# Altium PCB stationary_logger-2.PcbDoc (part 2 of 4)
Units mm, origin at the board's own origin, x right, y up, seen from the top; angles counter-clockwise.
Board outline 105 x 45 mm, 4 copper layers (Top Layer, Layer 2, Layer 3, Bottom Layer), stack 1.492 mm thick; 317 components, 187 nets, 816 pads, 302 vias.
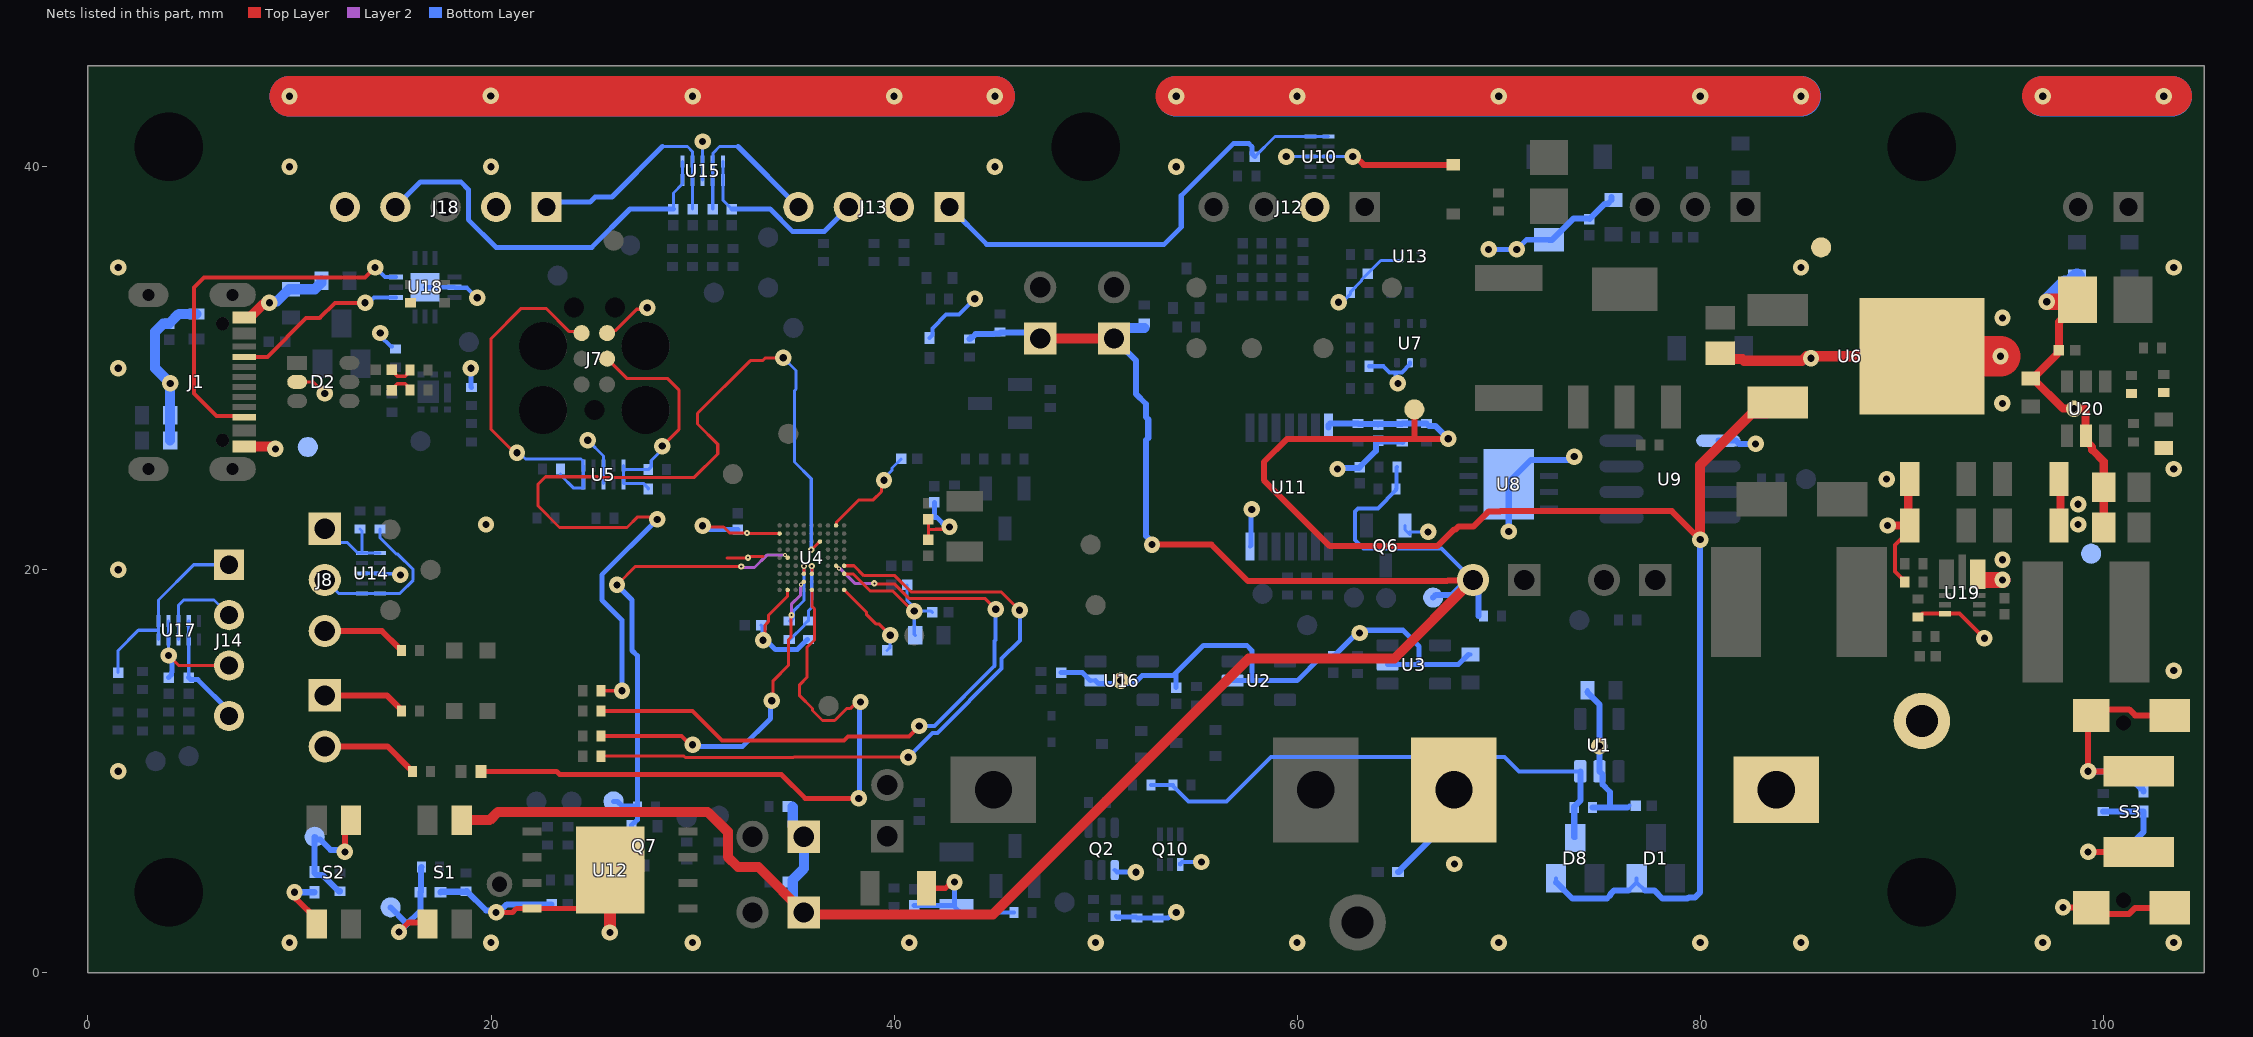
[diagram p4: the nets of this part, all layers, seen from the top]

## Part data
C1 C2: library part CAP-00124, "1µF ±10% 50V Ceramic Capacitor X7R 0805 (2012 Metric)", Manufacturer=Kemet, manufacturer_pn=C0805C105K5RACTU, Supplier Part Number 1=399-7409-1-ND, value_text=1u
C3 C9 C14: library part CAP-00070, "1µF ±10% 10V Ceramic Capacitor X7S 0402 (1005 Metric)", Manufacturer="Murata Electronics North America", manufacturer_pn=GCM155C71A105KE38D, Supplier Part Number 1=490-13409-1-ND, value_text=1u
C4 C13 C16 C17 C19 C20 C21 C22 C24 C25 C28 C29 C33 C34 C35 C42: library part CAP-00140, "0.1µF ±10% 10V Ceramic Capacitor X7R 0402 (1005 Metric)", Manufacturer="Samsung Electro-Mechanics America, Inc.", manufacturer_pn=CL05B104KP5NNNC, Supplier Part Number 1=1276-1002-1-ND, value_text=0.1u
C5: library part CAP-00099, "100pF ±5% 50V Ceramic Capacitor C0G, NP0 0402 (1005 Metric)", Manufacturer="TDK Corporation", manufacturer_pn=CGA2B2C0G1H101J050BA, Supplier Part Number 1=445-5596-1-ND, value_text=100p
C6 C11 C41: library part CAP-00138, "CAP CER 0.1UF 50V X7R 0603", Manufacturer="Samsung Electro-Mechanics America, Inc.", manufacturer_pn=CL10B104KB8NNNC, Supplier Part Number 1=1276-1000-1-ND, value_text=0.1u
C7: library part CAP-00114, "10000pF ±10% 50V Ceramic Capacitor X7R 0402 (1005 Metric)", Manufacturer=Kemet, manufacturer_pn=C0402C103K5RAC7867, Supplier Part Number 1=399-C0402C103K5RAC7867CT-ND, value_text=10000p
C8 C18 C43: library part CAP-00136, "CAP CER 4.7UF 16V X5R 0603", Manufacturer="Samsung Electro-Mechanics America, Inc.", manufacturer_pn=CL10A475KO8NNNC, Supplier Part Number 1=1276-1784-1-ND, value_text=4.7u
C10 C15: library part CAP-00137, "CAP CER 2.2UF 10V X5R 0603", Manufacturer="Samsung Electro-Mechanics America, Inc.", manufacturer_pn=CL10A225KP8NNNC, Supplier Part Number 1=1276-1085-1-ND, value_text=2.2u
C12 C23: library part CAP-00139, "CAP CER 47UF 10V X5R 1206", Manufacturer="Samsung Electro-Mechanics America, Inc.", manufacturer_pn=CL31A476MPHNNNE, Supplier Part Number 1=1276-3063-1-ND, value_text=47u
C26 C27: library part CAP-00102, "15pF ±1% 50V Ceramic Capacitor C0G, NP0 0402 (1005 Metric)", Manufacturer="AVX Corporation", manufacturer_pn=04025U150FAT2A, Supplier Part Number 1=478-10141-1-ND, value_text=15p
C30 C31 C32 C36: library part CAP-00142, "4.7 µF ±10% 50V Ceramic Capacitor X7R 1206 (3216 Metric)", Manufacturer=Kemet, manufacturer_pn=C1206C475K5RAC7800, Supplier Part Number 1=399-C1206C475K5RAC7800CT-ND, value_text=4.7u
C37: library part CAP-00029, "100µF Molded Tantalum - Polymer Capacitors 6.3V 1210 (3528 Metric) 55 mOhm 0.138\" L x 0.110\" W (3.50mm x 2.80mm)", Manufacturer="AVX Corporation", manufacturer_pn=TCJB107M006R0055, Supplier Part Number 1=478-9410-1-ND, value_text=100u
C38: library part CAP-00104, "47pF ±5% 50V Ceramic Capacitor C0G, NP0 0402 (1005 Metric)", Manufacturer="Wurth Electronics Inc", manufacturer_pn=885012005059, Supplier Part Number 1=732-7473-1-ND, value_text=47p
C39 C40: library part CAP-00031, "22µF 16V Ceramic Capacitor X5R 0805 (2012 Metric) 0.079\" L x 0.049\" W (2.00mm x 1.25mm)", Manufacturer="Murata Electronics North America", manufacturer_pn=GRM21BR61C226ME44L, Supplier Part Number 1=490-10747-1-ND, value_text=22u
D1 D8 D18: library part DIO-00052, "Diode Array 1 Pair Common Cathode Schottky 30 V 200mA (DC) Surface Mount TO-236-3, SC-59, SOT-23-3", Manufacturer="Nexperia USA Inc.", manufacturer_pn=BAT54C,215, Supplier Part Number 1=1727-2902-1-ND
D2: library part DIO-00054, "TVS DIODE 5.25VWM 17VC SOT23-6", Manufacturer=STMicroelectronics, manufacturer_pn=USBLC6-2SC6, Supplier Part Number 1=497-5235-1-ND
D3: library part DIO-00049, "8.5V (Typ) Clamp 6.3A (8/20µs) Ipp Tvs Diode Surface Mount 2-X1SON (1x.60)", Manufacturer="Texas Instruments", manufacturer_pn=TPD1E1B04DPYR, Supplier Part Number 1=296-47364-1-ND
D4 D5 D6 D9: library part DIO-00055, "TVS DIODE 3.6VWM 8.9VC 2X1SON", Manufacturer="Texas Instruments", manufacturer_pn=TPD1E04U04DPYR, Supplier Part Number 1=296-47224-1-ND
D7: library part DIO-00053, "DIODE SCHOTTKY 30V 200MA SOD523", Manufacturer="ON Semiconductor", manufacturer_pn=NSRLL30XV2T1G, Supplier Part Number 1=NSRLL30XV2T1GOSCT-ND
D10: library part DIO-00063, "DIODE SCHOTTKY 50V 1A SMA", Manufacturer="Diodes Incorporated", manufacturer_pn=B150-13-F, Supplier Part Number 1=B150-FDICT-ND
D11: library part LED-00025, "LED RED CLEAR 0402 SMD", Manufacturer="Rohm Semiconductor", manufacturer_pn=SML-P12VTT86R, Supplier Part Number 1=846-1168-1-ND
D12: library part LED-00007, "Green 571nm LED Indication - Discrete 2V 0603 (1608 Metric) 35mcd clear", Manufacturer="Lite-On Inc.", manufacturer_pn=LTST-C191KGKT, Supplier Part Number 1=160-1446-1-ND
D13: library part LED-00006, "Yellow 591nm LED Indication - Discrete 2.1V 0603 (1608 Metric) 104mcd clear", Manufacturer="Lite-On Inc.", manufacturer_pn=LTST-C191KSKT, Supplier Part Number 1=160-1448-1-ND
D14 D16: library part DIO-00040, "Diode Standard 100V 215mA (DC) Surface Mount SOD-123", Manufacturer="Nexperia USA Inc.", manufacturer_pn=BAS16GWJ, Supplier Part Number 1=1727-7320-1-ND
D15: library part DIO-00059, "DIODE ZENER 27V 300MW SOD323", Manufacturer="ON Semiconductor", manufacturer_pn=MM3Z27VT1G, Supplier Part Number 1=MM3Z27VT1GOSCT-ND
D17: library part DIO-00058, "TVS DIODE 15VWM 24VWM SOD323", Manufacturer="Nexperia USA Inc.", manufacturer_pn=PESD1LIN,115, Supplier Part Number 1=1727-3818-1-ND
D19: library part DIO-00057, "TVS DIODE 22VWM 31VC", Manufacturer=STMicroelectronics, manufacturer_pn=ESDA25P35-1U1M, Supplier Part Number 1=511-ESDA25P35-1U1M
F1: library part FUSE-00012, "Polymeric PTC Resettable Fuse 33V 1.1A Ih Surface Mount 2920 (7351 Metric), Concave", Manufacturer="Littelfuse Inc.", manufacturer_pn=2920L100PR, Supplier Part Number 1=F2868CT-ND
FB1: library part FER-00015, "FERRITE BEAD 220 OHM 0402 1LN", Manufacturer="TDK Corporation", manufacturer_pn=MPZ1005S221HT000, Supplier Part Number 1=445-MPZ1005S221HT000CT-ND, value_text=220
FB2: library part FER-00014, "FERRITE BEAD 600 OHM 0402 1LN", Manufacturer="Murata Electronics North America", manufacturer_pn=BLM15BD601SN1D, Supplier Part Number 1=490-1009-1-ND, value_text=600
FB3 FB4 FB5 FB8 FB9 FB10 FB11 FB12 FB13 FB14 FB15 FB16 FB17 FB18: library part FER-00013, "FERRITE BEAD 1 KOHM 0402 1LN", Manufacturer="Murata Electronics North America", manufacturer_pn=BLM15AX102SN1D, Supplier Part Number 1=490-5442-1-ND, value_text=1k
FB6 FB7 FB19 FB20: library part FER-00004, "FERRITE BEAD 220 OHM 0603 1LN 50m ohm", Manufacturer="Murata Electronics North America", manufacturer_pn=BLM18EG221SN1D, Supplier Part Number 1=490-3992-1-ND, value_text=220
J1: library part CONN-00185, "CONN RCP USB2.0 TYP C 24P SMD RA", Manufacturer=GCT, manufacturer_pn=USB4105-GF-A, Package=None, Supplier Part Number 1=2073-USB4105-GF-ACT-ND
J2 J3 J6 J9 J11 J15 J16 J17: library part CONN-00001, "2 Positions Header, Unshrouded Connector 0.100\" (2.54mm) Through Hole Gold", Manufacturer=3M, manufacturer_pn=961102-6404-AR, Supplier Part Number 1=3M9457-02-ND
J4 J5: library part CONN-00161, "BATTERY CONTACT CLIP 18650 SMD", Manufacturer="Keystone Electronics", manufacturer_pn=254, Supplier Part Number 1=36-254-ND
J7: library part NOBOM-00009, "Tag Connect TC2030 LEGS", Manufacturer="New Horizons"
J8: library part CONN-00030, "3 Positions Header, Unshrouded Connector 0.100\" (2.54mm) Through Hole Gold", Manufacturer=3M, manufacturer_pn=961103-6404-AR, Supplier Part Number 1=3M9457-03-ND
J10: library part CONN-00186, "CONN HEADER R/A 3POS 2.5MM", Manufacturer="JST Sales America Inc.", manufacturer_pn=S3B-XH-A(LF)(SN), Supplier Part Number 1=455-2250-ND
J12 J13 J14: library part CONN-00005, "4 Positions Header, Shrouded Connector 0.098\" (2.50mm) Through Hole, Right Angle Tin", Manufacturer="JST Sales America Inc.", manufacturer_pn=S4B-XH-A(LF)(SN), Supplier Part Number 1=455-2243-ND
J18: library part CONN-00187, "CONN HEADER R/A 5POS 2.5MM", Manufacturer="JST Sales America Inc.", manufacturer_pn=S5B-XH-A(LF)(SN), Supplier Part Number 1=455-2242-ND
J19: library part CONN-00192, "CONN HEADER R/A 2POS 2.5MM", Manufacturer="JST Sales America Inc.", manufacturer_pn=S2B-XH-A(LF)(SN), Supplier Part Number 1=455-S2B-XH-A-ND
JP1 JP2 JP3 JP4 JP6 JP8 JP9: library part MECH-00014, "2 (1 x 2) Position Shunt Connector Black Open Top 0.100\" (2.54mm) Gold", Manufacturer="Sullins Connector Solutions", manufacturer_pn=QPC02SXGN-RC, Supplier Part Number 1=S9337-ND
L1: library part IND-00035, "FIXED IND 6.8UH 3A 31 MOHM SMD", Manufacturer="Laird Technologies EMI", manufacturer_pn=TYS60456R8M-10, Supplier Part Number 1=240-TYS60456R8M-10CT-ND, value_text=6.8u
MTG1 MTG2 MTG3 MTG4 MTG5: library part NOBOM-00023, "Mounting hole, 3mm NPT", Manufacturer="New Horizons"
Q1 Q13: library part FET-00028, "MOSFET P-CH 30V 3.8A SOT23", Manufacturer="Diodes Incorporated", manufacturer_pn=DMP3099L-7, Supplier Part Number 1=DMP3099L-7DICT-ND
Q2: library part FET-00000, "MOSFET N/P-CH 20V SOT363", Manufacturer="Diodes Incorporated", manufacturer_pn=DMG1016UDW-7, Supplier Part Number 1=DMG1016UDW-7DICT-ND
Q3 Q6: library part BJT-00000, "TRANS NPN 40V 0.2A SOT23", Manufacturer="ON Semiconductor", manufacturer_pn=MMBT3904LT1G, Supplier Part Number 1=MMBT3904LT1GOSCT-ND
Q4 Q5 Q7 Q8 Q9: library part FET-00029, "MOSFET P-CH 20V 820MA SOT323", Manufacturer="Diodes Incorporated", manufacturer_pn=DMG1013UW-7, Supplier Part Number 1=DMG1013UW-7DICT-ND
Q10: library part FET-00030, "MOSFET N/P-CH 20V SOT563", Manufacturer="Vishay Siliconix", manufacturer_pn=SI1016X-T1-GE3, Supplier Part Number 1=781-SI1016X-T1-GE3
Q11: library part FET-00032, "MOSFET N-CH 55V 3.8A SOT223", Manufacturer="Infineon Technologies", manufacturer_pn=IRLL2705TRPBF, Supplier Part Number 1=IRLL2705PBFCT-ND
Q12: library part FET-00031, "MOSFET N-Ch 30 V 0.021 Ohm 6 A", Manufacturer=STMicroelectronics, manufacturer_pn=STL6N3LLH6, Supplier Part Number 1=511-STL6N3LLH6
R1 R3 R4 R8 R9 R10 R11 R12 R13 R21 R26 R27 R28 R29 R34 R45 R48 R51 R52 R53 R54 R55 R57 R58 R60 R63 R65 R67 R71 R73 R76 R82 R83 R85 R86 R97 R105: library part RES-00093, "0.0 Ohm Jumper 0.063W, 1/16W Chip Resistor 0402 (1005 Metric) Moisture Resistant Thick Film", Manufacturer=Yageo, manufacturer_pn=RC0402JR-070RL, Supplier Part Number 1=311-0.0JRCT-ND, value_text=0
R2 R118: library part RES-00073, "RES SMD 300K OHM 1% 1/16W 0402", Manufacturer="Vishay Dale", manufacturer_pn=CRCW0402300KFKED, Supplier Part Number 1=541-300KLCT-ND, value_text=300k
R5: library part RES-00197, "RES 68K OHM 1% 1/16W 0402", Manufacturer=Yageo, manufacturer_pn=RC0402FR-0768KL, Supplier Part Number 1=311-68.0KLRCT-ND, value_text=68k
R6: library part RES-00202, "RES SMD 330 OHM 1% 1/10W 0603", Manufacturer="Panasonic Electronic Components", manufacturer_pn=ERJ-3EKF3300V, Supplier Part Number 1=P330HCT-ND, value_text=330
R7 R64 R104: library part RES-00198, "RES 33K OHM 1% 1/16W 0402", Manufacturer=Yageo, manufacturer_pn=RC0402FR-0733KL, Supplier Part Number 1=311-33.0KLRCT-ND, value_text=33k
R14 R25 R30 R32 R33: library part RES-00090, "1k Ohm ±1% 0.063W, 1/16W Chip Resistor 0402 (1005 Metric) Moisture Resistant Thick Film", Manufacturer=Yageo, manufacturer_pn=RC0402FR-071KL, Supplier Part Number 1=311-1.00KLRCT-ND, value_text=1k
R15 R17 R22 R31 R49 R69 R74 R98 R99: library part RES-00095, "100k Ohm ±1% 0.063W, 1/16W Chip Resistor 0402 (1005 Metric) Moisture Resistant Thick Film", Manufacturer=Yageo, manufacturer_pn=RC0402FR-07100KL, Supplier Part Number 1=311-100KLRCT-ND, value_text=100k
R16: library part RES-00199, "RES 8.2K OHM 1% 1/16W 0402", Manufacturer=Yageo, manufacturer_pn=RC0402FR-078K2L, Supplier Part Number 1=311-8.20KLRCT-ND, value_text=8.2k
R18 R41 R70 R95: library part RES-00094, "10k Ohm ±1% 0.063W, 1/16W Chip Resistor 0402 (1005 Metric) Moisture Resistant Thick Film", Manufacturer=Yageo, manufacturer_pn=RC0402FR-0710KL, Supplier Part Number 1=311-10.0KLRCT-ND, value_text=10k
R19 R20 R96: library part RES-00205, "RES 2.74K OHM 1% 1/16W 0402", Manufacturer=Yageo, manufacturer_pn=RC0402FR-072K74L, Supplier Part Number 1=YAG3104CT-ND, value_text=2740
R23 R24 R77 R91 R92: library part RES-00170, "4.75k ±1% 0.063W, 1/16W Chip Resistor 0402 (1005 Metric) - Thick Film", Manufacturer=Yageo, manufacturer_pn=RC0402FR-074K75L, Supplier Part Number 1=311-4.75KLCT-ND, value_text=4.75k
R35 R36 R37 R38 R39 R40 R42 R59 R61 R62 R66 R68 R87 R88 R89 R90 R93 R94: library part RES-00169, "47.5 ±1% 0.063W, 1/16W Chip Resistor 0402 (1005 Metric) - Thick Film", Manufacturer=Yageo, manufacturer_pn=RC0402FR-0747R5L, Supplier Part Number 1=311-47.5LRCT-ND, value_text=47.5
R43: library part RES-00203, "RES 402 OHM 1% 1/16W 0402", Manufacturer=Yageo, manufacturer_pn=RC0402FR-07402RL, Supplier Part Number 1=YAG3152CT-ND, value_text=402
R44 R46 R50 R116 R117: library part RES-00111, "100 Ohms ±1% 0.063W, 1/16W Chip Resistor 0402 (1005 Metric) Moisture Resistant Thick Film", Manufacturer=Yageo, manufacturer_pn=RC0402FR-07100RL, Supplier Part Number 1=311-100LRCT-ND, value_text=100
R47 R56 R72 R78 R101 R106: library part RES-00137, "1 MOhms ±1% 0.063W, 1/16W Chip Resistor 0402 (1005 Metric) Automotive AEC-Q200 Thick Film", Manufacturer="Vishay Dale", manufacturer_pn=RC0402FR-071ML, Supplier Part Number 1=541-1.00MLCT-ND, value_text=1M
R75: library part RES-00204, "RESISTOR FUSIBLE 10 OHMS 1206", Manufacturer="Kamaya, Inc", manufacturer_pn=FRC32C2B100JTP, Supplier Part Number 1=2315-FRC32C2B100JTPCT-ND, value_text=10
R79 R80 R81: library part RES-00201, "RES 33 OHM 1% 1/16W 0402", Manufacturer=Yageo, manufacturer_pn=RC0402FR-0733RL, Supplier Part Number 1=311-33.0LRCT-ND, value_text=33
R84: library part RES-00196, "1 kOhms ±1% 1W Chip Resistor 2512 (6432 Metric) Automotive AEC-Q200 Thick Film", Manufacturer="Stackpole Electronics Inc", manufacturer_pn=RMCF2512FT1K00, Supplier Part Number 1=RMCF2512FT1K00CT-ND, value_text=1000
R100: library part RES-00214, "RES 178K OHM 1% 1/16W 0402", Manufacturer=Yageo, manufacturer_pn=RC0402FR-07178KL, Supplier Part Number 1=YAG3010CT-ND, value_text=178k
R102 R103: library part RES-00213, "RES 23.7K OHM 1% 1/16W 0402", Manufacturer=Yageo, manufacturer_pn=RC0402FR-0723K7L, Supplier Part Number 1=YAG3067CT-ND, value_text=23.7k
S1 S2: library part SW-00011, "Tactile Switch SPST-NO Top Actuated Surface Mount", Manufacturer="Panasonic Electronic Components", manufacturer_pn=EVQ-P2402W, Supplier Part Number 1=P11081SCT-ND
S3: library part SW-00012, "SWITCH TACTILE SPST-NO 0.05A 24V", Manufacturer="TE Connectivity ALCOSWITCH Switches", manufacturer_pn=1571300-2, Supplier Part Number 1=450-2127-ND
TP1 TP2 TP3 TP4 TP5 TP7 TP8 TP9 TP10 TP11 TP13 TP14 TP15 TP16 TP17 TP18 TP19 TP20 TP21 TP22 TP24 TP25 TP26 TP27 TP28 TP29 TP30 TP31 TP33 TP34 TP35 TP36 TP37 TP38 TP39 TP40 TP41 TP43 TP44 TP45 TP46 TP47 TP49 TP50 TP53: library part NOBOM-00001, "Test point, SMD, 1mm dia (0.040\")", Manufacturer="New Horizons"
TP6 TP12: library part CONN-00028, "TEST POINT PC MULTI PURPOSE BLK", Manufacturer="Keystone Electronics", manufacturer_pn=5011, Supplier Part Number 1=36-5011-ND
TP23: library part NOBOM-00007, "Test point, TH, 0.78mm (30mil) hole, 1.27mm (50 mil) pad", Manufacturer="New Horizons"
U1: library part ICPWR-00061, "IC REG LINEAR 3.3V 200MA SOT23-5", Manufacturer="Texas Instruments", manufacturer_pn=TPS7A2433DBVR, Supplier Part Number 1=296-TPS7A2433DBVRCT-ND
U2 U16: library part ICPWR-00045, "OR Controller Source Selector Switch P-Channel 1:1 SOT-23-5", Manufacturer="Maxim Integrated", manufacturer_pn=MAX40203AUK+T, Supplier Part Number 1=175-MAX40203AUK+TCT-ND
U3: library part ICPWR-00062, "IC REG LINEAR 1.8V 200MA SOT23-5", Manufacturer="Texas Instruments", manufacturer_pn=TPS7A0518PDBVR, Supplier Part Number 1=296-TPS7A0518PDBVRCT-ND
U4: library part MCU-00028, "IC MCU 32BIT 512KB FLASH WLCSP72", Manufacturer=STMicroelectronics, Supplier Part Number 1=511-STM32L476JEY6TR
U5 U10 U14 U15 U17: library part DIO-00056, "TVS DIODE 3VC DFN2510A-10", Manufacturer="Nexperia USA Inc.", Supplier Part Number 1=1727-7814-1-ND
U6: library part ICPWR-00063, "IC REG LINEAR 5V 500MA DPAK", Manufacturer="ON Semiconductor", manufacturer_pn=NCV78M05BDTRKG, Supplier Part Number 1=NCV78M05BDTRKGOSCT-ND
U7: library part ICANA-00030, "Temperature Sensor Digital, Local -55°C ~ 150°C 16 b 6-WSON (2x2)", Manufacturer="Texas Instruments", manufacturer_pn=TMP117NAIDRVR, Supplier Part Number 1=296-51836-1-ND
U8: library part ICXCV-00033, "LIN Transceiver", Manufacturer="Microchip Technology", manufacturer_pn=MCP2003-E/MD, Supplier Part Number 1=579-MCP2003EMD
U9: library part ICXCV-00029, "LIN Transceiver", Manufacturer="Microchip Technology", manufacturer_pn=MCP2003T-E/SN, Supplier Part Number 1=579-MCP2003TESN
U11: library part ICXCV-00032, "IC TRNSLTR BIDIRECTIONAL", Manufacturer="NXP Semiconductors", manufacturer_pn=NTS0104PW,118, Supplier Part Number 1=771-NTS0104PW118
U12: library part ICDIG-00028, "IC FLASH 1GBIT SPI 104MHZ 8WSON 1.8V", Manufacturer="Winbond Electronics", manufacturer_pn=W25N01GWZEIG, Supplier Part Number 1=454-W25N01GWZEIG
U13: library part ICANA-00040, "TEMP SENSOR WLCSP6 I2C", Manufacturer=AMS, manufacturer_pn=AS6212-AWLT-S, Supplier Part Number 1=961-AS6212-AWLT-SCT-ND
U18: library part ICXCV-00034, "USB-C interface IC Overvoltage Protection", Manufacturer=STMicroelectronics, manufacturer_pn=TCPP01-M12, Supplier Part Number 1=511-TCPP01-M12
U19: library part ICPWR-00067, "IC REG BUCK ADJ 3.5A 13DFN", Manufacturer="Diodes Incorporated", manufacturer_pn=AP63357DV-7, Supplier Part Number 1=31-AP63357DV-7CT-ND
U20: library part ICPWR-00068, "IC PWR SWITCH N-CHAN 1:1 SOT23-6", Manufacturer="Texas Instruments", manufacturer_pn=TPS2553DBVR, Supplier Part Number 1=296-32464-1-ND
Y1: library part XTAL-00000, "32.768kHz ±20ppm Crystal 12.5pF 55 kOhm -40°C ~ 85°C Surface Mount 2-SMD", Manufacturer="Abracon LLC", manufacturer_pn=ABS07L-32.768KHZ-T, Supplier Part Number 1=535-12058-1-ND, value_text=32768
Z1 Z2 Z3 Z4 Z5 Z6 Z11 Z12: "Fiducial, 1mm dia, 3mm solder mask opening", Manufacturer="New Horizons"

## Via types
v1: diameter 0.813, hole 0.356, Top Layer to Bottom Layer, tented both sides, 238 vias
v2: diameter 0.305, hole 0.102, Top Layer to Layer 2, tented both sides, 29 vias
v3: diameter 0.203, hole 0.102, Top Layer to Layer 2, tented both sides, 27 vias
v4: diameter 0.305, hole 0.13, Top Layer to Bottom Layer, tented both sides, 8 vias

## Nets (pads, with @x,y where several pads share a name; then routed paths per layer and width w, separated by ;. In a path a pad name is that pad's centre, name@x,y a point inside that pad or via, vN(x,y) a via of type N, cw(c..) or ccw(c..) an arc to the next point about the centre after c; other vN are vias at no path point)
1V8: J3.2 J6.1 J9.1 J11.1 J15.1 R13.2 R21.1 R34.1 R45.1 R54.1 R63.2 R69.1 R71.1 S1.4 TP5.1 | length 117.9
  Top Layer w0.3: v1(52.799,21.25) 55.75,21.25 57.555,19.445 67.444,19.445 67.475,19.476 68.706,19.476 J3.2@68.73,19.5
  Top Layer w0.5: S1.4@18.55,7.575 19.931,7.575 20.339,7.983 30.75,7.983 31.233,7.5 31.25,7.5 31.75,7 31.75,5.75 32.25,5.25 33.27,5.25 35.62,2.9 44.9,2.9 57.6,15.6 64.83,15.6 J3.2@68.706,19.476 ; J11.1@47.25,31.48 J9.1@50.912,31.48
  Bottom Layer w0.2: R63.2@64.965,25.1 64.94,25.075 64.94,24.025 R69.1@64.915,24 64.915,23.95 64.008,23.043 63.026,23.043 62.878,22.895 62.878,21.486 63.302,21.062 67.168,21.062 J3.2@68.73,19.5
  Bottom Layer w0.3: R34.1@43.75,31.45 43.825,31.525 43.875,31.525 44.05,31.7 44.949,31.7 44.974,31.725 45.225,31.725 45.275,31.775 46.955,31.775 J11.1@47.25,31.48 ; J9.1@51.612,30.78 52,30.392 52,28.728 52.5,28.228 52.5,27.571 52.611,27.46 52.611,26.54 52.5,26.429 52.5,21.682 52.799,21.383 v1(52.799,21.25) ; TP5.1@66.75,18.625 66.88,18.755 67.7,18.755 68.445,19.5 J3.2@68.73,19.5 68.73,19.148 69,18.878 69,17.7
  Bottom Layer w0.5: 34.95,8.25 34.97,8.23 34.97,7.3 J6.1@35.52,6.75 35.52,5.17 34.95,4.6 34.95,4.5 34.97,4.48 34.97,3.55 J15.1@35.52,3 ; J9.1@50.912,31.48 51.429,31.997 52.412,31.997
5V_LIN: C34.2 D1.2 D8.2 R70.2 R77.1 R98.1 TP11.1 U6.3 U11.14 | length 77.8
  Top Layer w0.2: 65.75,26.5 65.818,26.568
  Top Layer w0.3: 65.818,26.568 TP11.1@65.818,27.956 ; v1(67.5,26.5) 65.75,26.5 59.499,26.5 58.348,25.348 58.348,24.45 61.627,21.171 66.961,21.171 67.797,22.007 67.868,22.007 68.017,22.156 68.756,22.156 69.5,22.9 70.073,22.9 70.082,22.909 78.591,22.909 v1(80,21.5)
  Top Layer w0.5: v1(80,21.5) 80,25.2 82.558,27.758 83.3,27.758 U6.3@83.85,28.308
  Bottom Layer w0.2: R70.2@66.419,27.25 R70.2@66.544,27.125 ; D8.2@72.85,4.491 D8.2@72.85,4.691 ; D1.2@76.45,4.091 D1.2@76.85,4.491 ; D1.2@76.85,4.691 D1.2@76.85,4.491 ; D1.2@77.25,4.091 D1.2@76.85,4.491
  Bottom Layer w0.3: U11.14@61.56,27.05 61.56,27.175 61.635,27.25 R77.1@63.015,27.25 63.04,27.225 63.99,27.225 C34.2@64.015,27.2 64.04,27.225 65.192,27.225 R98.1@65.217,27.25 R70.2@66.419,27.25 ; R70.2@66.544,27.125 66.875,27.125 v1(67.5,26.5) ; D8.2@72.85,4.491 73.652,3.688 75.375,3.688 75.552,3.865 75.552,3.915 75.728,4.091 D1.2@76.45,4.091 ; D1.2@77.25,4.091 77.722,4.091 78.125,3.688 79.375,3.688 79.437,3.75 79.75,3.75 80,4 v1(80,21.5)
AMB_SCL: FB16.2 J14.4 U17.4 U17.7 | length 5.7
  Bottom Layer w0.152: FB16.2@5,14.65 U17.7@5,16.55 U17.4@5,17.45
  Bottom Layer w0.25: FB16.2@5,14.65 5.1,14.55 5.45,14.55 7,13 J14.4@7,12.75
AMB_SDA: FB15.2 J14.3 U17.2 U17.9 | length 6.1
  Top Layer w0.152: v1(4,15.75) 4.5,15.25 J14.3@7,15.25
  Bottom Layer w0.152: v1(4,15.75) U17.9@4,16.55 U17.2@4,17.45
  Bottom Layer w0.25: FB15.2@4,14.65 4.135,14.785 4.135,14.9 4.166,14.931 4.166,15.432 4,15.598 v1(4,15.75)
AMB_VDD: FB14.2 J14.1 U17.1 U17.10 | length 9.7
  Bottom Layer w0.152: FB14.2@1.5,14.9 1.5,16 2.5,17 3.5,17 ; U17.10@3.5,16.55 3.5,17 ; J14.1@7,20.25 5.25,20.25 3.5,18.5 3.5,17
BTN_BOOT0: D4.1 R30.2 S1.1 TP20.1 | length 6.5
  Top Layer w0.3: v1(15.435,2.028) 15.907,2.5 16.775,2.5 S1.1@16.85,2.425
  Bottom Layer w0.3: TP20.1@15.017,3.25 15.017,3.241 15.75,2.509 15.75,2.343 ; v1(15.435,2.028) 15.75,2.343 ; R30.2@16.55,5.25 16.525,5.225 16.525,4.025 D4.1@16.5,4 16.5,3.093 15.75,2.343
BTN_nRST: D5.1 R32.2 S2.1 TP21.1 | length 7
  Top Layer w0.3: v1(12.75,6) 12.75,7.175 12.7,7.225 S2.1@13.05,7.575
  Bottom Layer w0.3: R32.2@12.5,4.05 12.45,4.05 11.65,4.85 11.35,4.85 11.25,4.95 D5.1@11.25,5 11.25,6.616 TP21.1@11.25,6.75 11.384,6.616 11.517,6.616 12.035,6.098 12.652,6.098 v1(12.75,6)
BTN_USER: D6.1 R33.2 S3.1 TP22.1 | length 8.7
  Top Layer w0.3: v1(99.25,6) S3.1@101.75,6
  Bottom Layer w0.3: v1(99.25,6) TP22.1@101,6 102,7 D6.1@102,8 R33.2@100,8
CC1c: J1.A5 U18.7 | length 8.7
  Top Layer w0.2: J1.A5@7.755,30.57 8.9,30.57 10.83,32.5 11.5,32.5 12.25,33.25 v1(13.75,33.25)
  Bottom Layer w0.2: v1(13.75,33.25) 13.916,33.25 14.186,33.52 U18.7@15.28,33.52
CC2c: J1.B5 U18.9 | length 18.9
  Top Layer w0.2: J1.B5@7.755,27.57 7.705,27.62 6.38,27.62 5.25,28.75 5.25,34 5.75,34.5 13.75,34.5 v1(14.25,35)
  Bottom Layer w0.2: v1(14.25,35) 14.73,34.52 U18.9@15.28,34.52
D_N: FB9.2 R8.2 | length 1.2
  Top Layer w0.178: FB9.2@15.08,28.92 15.251,29.091 15.251,29.125 15.356,29.229 15.74,29.229 15.844,29.125 15.844,29.056 R8.2@15.98,28.92
D_P: FB10.2 R9.2 | length 1.2
  Top Layer w0.178: FB10.2@15.08,29.92 15.251,29.749 15.251,29.715 15.356,29.61 15.74,29.61 15.844,29.715 15.844,29.784 R9.2@15.98,29.92
D_RX: J8.2 R38.1 U14.5 U14.6 | length 8.2
  Bottom Layer w0.152: J8.2@11.74,19.529 12.442,18.828 U14.6@13.598,18.828 U14.5@14.498,18.828 15.472,18.828 16.133,19.488 16.133,20.012 15.352,20.793 15.281,20.793 14.5,21.574 R38.1@14.5,22.028
D_TX: J8.1 R36.1 U14.1 U14.10 | length 4.6
  Bottom Layer w0.152: J8.1@11.688,22.069 12.412,21.345 12.881,21.345 13.398,20.828 U14.10@13.598,20.828 ; R36.1@13.5,22.028 13.598,21.93 U14.10@13.598,20.828 ; U14.1@14.498,20.828 U14.10@13.598,20.828
DBG_UART_RX: J7.3 R35.1 R42.2 U5.1 U5.10 | length 12.3
  Top Layer w0.152: J7.3@25.762,30.473 26.735,29.5 28.75,29.5 29.321,28.929 29.321,26.956 v1(28.5,26.135)
  Bottom Layer w0.152: U5.10@26.577,25.172 U5.10@26.577,24.996 ; R42.2@27.8,24 27.8,24.05 27.578,24.272 U5.1@26.577,24.272 U5.10@26.577,24.996 ; v1(28.5,26.135) 28.5,25.972 27.949,25.421 27.949,25.121 R35.1@27.8,24.972 26.601,24.972 U5.10@26.577,24.996
DBG_UART_TX: J7.6 R40.1 U5.5 U5.6 | length 18.1
  Top Layer w0.152: v1(21.29,25.812) 21.16,25.812 20,26.972 20,31.472 21.5,32.972 22.725,32.972 23.863,31.835 24.4,31.835 J7.6@24.492,31.743
  Bottom Layer w0.152: v1(21.29,25.812) 21.397,25.812 21.709,25.5 22.23,25.5 22.231,25.501 23.772,25.501 23.773,25.5 24.464,25.5 24.553,25.411 24.553,25.196 U5.6@24.577,25.172 U5.5@24.577,24.272 24.577,24.072 24.553,24.048 24.102,24.048 23.45,24.7 R40.1@23.45,24.75
DEBUG_LED: D11.A U4.J5 | length 33.7
  Top Layer w0.152: U4.J5@35.92,19 35.92,18.188 36.047,18.061 36.047,16.517 35.672,16.142 35.672,14.653 35.317,14.297 35.317,13.749 35.951,13.115 35.951,13.019 36.448,12.521 37.052,12.521 37.64,13.11 37.822,13.11 38.153,13.44 v1(38.331,13.44)
  Top Layer w0.25: D11.A@19.5,10 23.25,10 23.405,9.845 34.405,9.845 35.591,8.659 v1(38.25,8.659)
  Bottom Layer w0.152: v1@38.291,13.399 v1(38.331,13.44)
  Bottom Layer w0.25: v1(38.25,8.659) 38.291,8.699 v1@38.291,13.399
DOORF_C: FB18.2 J18.4 U15.5 U15.6 | length 19.9
  Bottom Layer w0.152: FB18.2@29.05,37.9 29.05,38.7 29.5,39.15 U15.5@29.5,39.35 U15.6@29.5,40.25
  Bottom Layer w0.25: J18.4@15.25,38 16.5,39.25 18.5,39.25 18.875,38.875 18.875,37.375 20.25,36 25,36 26.9,37.9 FB18.2@29.05,37.9
DOORV_C: FB17.2 J18.1 U15.4 U15.7 | length 11.4
  Bottom Layer w0.152: 28.5,41 29.75,41 30,40.75 U15.7@30,40.25 U15.4@30,39.35 FB17.2@30,37.9
  Bottom Layer w0.25: J18.1@22.75,38 22.996,38.246 24.918,38.246 25.172,38.5 26,38.5 28.5,41
FLASH_PWR_nEN: Q7.G R72.2 TP31.1 U4.E2 | length 22.8
  Top Layer w0.152: v1(26.25,19.25) 27.168,20.168 v2(32.415,20.168)
  Layer 2 w0.152: v2(32.415,20.168) 32.444,20.139 32.523,20.139 32.545,20.117 33.075,20.117 33.685,20.727 34.447,20.727 34.574,20.727 v3(34.583,20.737)
  Bottom Layer w0.25: TP31.1@26.077,8.508 26.28,8.508 26.513,8.275 R72.2@27.26,8.275 ; v1(26.25,19.25) 27,18.5 27,16 27.26,15.74 R72.2@27.26,8.275 ; Q7.G@26.96,7.275 26.96,7.325 27.085,7.45 27.114,7.45 27.26,7.596 R72.2@27.26,8.275
FRZ_SCL: FB13.2 J13.4 U15.2 U15.9 | length 8.4
  Bottom Layer w0.152: FB13.2@31,37.9 U15.2@31,39.35 U15.9@31,40.25 31.024,40.274 31.024,40.685 31.339,41 32.25,41
  Bottom Layer w0.25: 32.25,41 J13.4@35.25,38
FRZ_SDA: FB12.2 J13.3 U15.1 U15.10 | length 9.3
  Bottom Layer w0.152: U15.10@31.5,40.25 U15.1@31.5,39.35 31.5,38.35 FB12.2@31.95,37.9
  Bottom Layer w0.25: FB12.2@31.95,37.9 33.85,37.9 34.953,36.797 36.547,36.797 J13.3@37.75,38
FRZ_VDD: FB11.2 J13.1 U10.5 U10.6 | length 23.4
  Bottom Layer w0.152: FB11.2@57.9,40.5 58.9,41.5 U10.5@60.657,41.5 U10.6@61.557,41.5
  Bottom Layer w0.25: J13.1@42.75,38 44.598,36.152 53.402,36.152 54.25,37 54.25,38.562 56.834,41.146 57.604,41.146 57.765,40.985 57.765,40.635 FB11.2@57.9,40.5
GND: C1.2 C2.2 C3.1 C4.1 C5.2 C6.2 C7.1 C8.1 C9.1 C10.2 C11.2 C12.1 C13.1 C14.1 C15.2 C16.1 C17.2 C18.1 C19.1 C20.1 C21.1 C22.1 C23.1 C24.1 C25.1 C26.1 C27.1 C29.1 C30.1 C31.1 C32.1 C33.1 C34.1 C35.1 C36.1 C37.- C39.2 C40.2 C41.1 C42.1 C43.1 D2.2 D3.1 D4.2 D5.2 D6.2 D9.2 D15.A D19.A FB7.1 FB20.1 J1.A1_B12 J1.B1_A12 J5.1 J7.5 J8.3 J12.2 J13.2 J14.2 J17.1 J17.2 J18.2 J18.5 Q2.1 Q6.2 Q10.1 R4.2 R6.2 R7.1 R14.2 R17.2 R18.2 R27.1 R31.2 R43.2 R44.1 R46.1 R49.2 R52.2 R96.1 R98.2 R102.2 R103.2 R104.2 R106.2 R116.1 S2.4 S3.2 S3.MNT TP2.1 TP4.1 TP6.1 TP53.1 U1.2 U2.2 U3.2 U4.A8 U4.B1 U4.G9 U4.J2 U4.J9 U5.3 U5.8 U6.4 U7.2 U8.5 U8.9 U9.5 U10.3 U10.8 U11.7 U12.4 U12.9 U13.A1 U14.3 U14.8 U15.3 U15.8 U16.2 U17.3 U17.8 U18.2 U18.13 U19.4 U19.8 U20.2 | length 404.8
  Top Layer w0.152: D2.2@10.38,29.32 11.18,29.32 v1(11.75,28.75) ; U12.9@24.286,3.195 25.731,3.195 U12.9@25.9,3.026 ; J7.5@25.762,31.743 25.886,31.867 26.167,31.867 27.228,32.928 27.678,32.928 v1(27.75,33) ; v1@30.429,22.038 30.518,22.127 31.545,22.127 31.853,21.819 v2(32.7,21.819) ; 31.719,20.583 32.728,20.583 v2(32.745,20.6) 32.786,20.6 32.837,20.651 33.482,20.651 ; v2@32.711,21.811 32.721,21.8 U4.B1@34.32,21.8 ; v1(33.5,16.5) 33.591,16.591 33.591,17.255 33.761,17.425 33.761,17.73 34.706,18.675 34.706,18.986 U4.J2@34.72,19 ; U4.A8@37.12,22.2 37.134,22.214 37.134,22.347 38.257,23.47 38.968,23.47 39.374,23.876 39.374,24.316 v1(39.5,24.442) ; U4.J9@37.52,19 38.641,17.879 38.641,17.77 39.092,17.318 39.239,17.318 v1(39.807,16.75) ; U4.G9@37.52,19.8 37.965,19.8 38.816,18.949 39.939,18.949 40.937,17.951 v1(41,17.951) ; C27.1@41.705,21.5 41.705,22 ; C26.1@41.705,22.5 41.705,22 ; v1(42.75,22.127) 42.634,22.011 42.05,22.011 42.039,22 41.705,22
  Top Layer w0.2: R102.2@90.15,19.4 90.15,19.45 89.825,19.775 89.821,19.775 89.675,19.921 89.675,21.225 90.325,21.875 C30.1@90.325,22.2 ; R104.2@90.8,17.65 90.85,17.65 91.025,17.825 U19.4@92.152,17.825 92.875,17.825 v1(94.1,16.6)
  Top Layer w0.25: v1(20.25,3) 21.063,3 21.258,3.195 U12.4@22.04,3.195 U12.9@24.286,3.195
  Top Layer w0.254: C23.1@41.6,4.2 42.549,4.2 42.849,4.5 v1(43,4.5)
  Top Layer w0.3: v1(10.25,4) 10.348,3.902 10.348,3.652 11.35,2.65 S2.4@11.35,2.425 ; J17.2@11.75,11.23 14.87,11.23 15.975,10.125 16.025,10.125 16.1,10.05 R116.1@16.1,10 ; J17.1@11.75,13.77 14.83,13.77 15.55,13.05 R46.1@15.55,13 ; J8.3@11.75,16.96 14.59,16.96 15.425,16.125 15.475,16.125 15.55,16.05 R44.1@15.55,16 ; v1(62.757,40.5) 62.895,40.5 63.299,40.096 D15.A@67.75,40.096 ; v1(98,3.25) 99.375,3.25 99.702,2.923 101.281,2.923 101.583,3.225 S3.MNT@103.3,3.225 ; S3.2@101.75,10 v1(99.25,10) 99.25,12.625 99.702,13.077 101.281,13.077 101.583,12.775 S3.MNT@103.3,12.775
  Top Layer w0.4: v1(89.3,22.2) 90.325,22.2 C31.1@90.325,24.5 ; C41.1@96.4,29.5 C41.1@96.5,29.5 ; C36.1@97.875,22.2 C32.1@97.875,24.5 ; C37.-@98.725,33.4 98.725,33.225 97.8,32.3 C42.1@97.8,30.9 97.74,30.84 97.74,30.74 C41.1@96.5,29.5 ; C40.2@100.025,22.1 C39.2@100.025,24.1 100.025,25.38 99.45,25.955 99.45,26.1 99.15,26.4 U20.2@99.15,26.65 99.125,26.675 99.125,27.975 99.1,28 98,28 C41.1@96.5,29.5 ; R103.2@101.4,28.75 101.45,28.75 R103.2@101.475,28.775 ; C43.1@103,25.95 103.025,25.95 C43.1@103.15,26.075
  Top Layer w0.5: J1.B1_A12@7.755,26.12 9.095,26.12 9.215,26 v1(9.3,26) ; J1.A1_B12@7.755,32.52 8.03,32.52 8.7,33.19 8.94,33.19 v1(9,33.25) ; C2.2@81,30.875 81.411,30.464 82.09,30.464 82.181,30.372 85.053,30.372 85.278,30.598 U6.4@91,30.598
  Top Layer w0.6: v1(25.9,2) U12.9@25.9,3.026
  Top Layer w0.8: U19.8@93.797,19.502 94.998,19.502 v1(95,19.5) ; v1(97.2,33.3) 97.202,33.302 C37.-@98.627,33.302
  Top Layer w2: v1(10,43.5) v1(30,43.5) v1(40,43.5) v1(45,43.5) ; v1@53.978,43.51 60,43.51 70,43.51 v1@84.978,43.51 ; U6.4@91,30.598 91.002,30.6 v1(94.9,30.6) ; v1@96.978,43.51 103,43.51 v1@103.4,43.51
  Bottom Layer w0.152: U17.8@4.5,16.55 U17.3@4.5,17.45 4.5,18.25 4.75,18.5 6.25,18.5 J14.2@7,17.75 ; U14.8@13.598,19.828 U14.3@14.498,19.828 14.522,19.804 15.446,19.804 v1(15.5,19.75) ; v1(20.25,3) v1@20.389,3 ; v1(24.801,26.427) 24.801,26.421 25.577,25.646 U5.8@25.577,25.172 U5.3@25.577,24.272 ; U15.3@30.5,39.35 U15.8@30.5,40.25 v1(30.5,41.25) ; C19.1@33.4,17.25 C19.1@33.5,17.15 ; R43.2@35.7,16.55 R43.2@35.75,16.55 ; v1(39.5,24.442) 39.5,24.542 39.899,24.941 39.899,25.049 C21.1@40.35,25.5 ; C22.1@39.65,16 39.807,16.157 v1(39.807,16.75) ; C17.2@40.65,19.25 40.65,18.479 41,18.129 v1(41,17.951) ; C18.1@41.05,16.75 41,16.8 v1(41,17.951) ; C20.1@41.9,17.89 41.84,17.951 v1(41,17.951) ; v1(59.457,40.5) U10.3@60.657,40.5 U10.8@61.557,40.5 v1(62.757,40.5) ; v1(62.057,33.274) 62.23,33.274 62.657,33.7 R4.2@62.657,33.75 62.657,33.8 63.195,34.339 63.195,34.389 C29.1@63.507,34.7 64.156,35.35 U13.A1@65.207,35.35 ; Q6.2@65.348,22.191 65.348,21.991 65.589,21.75 65.589,21.88 v1(66.5,21.88)
  Bottom Layer w0.2: v1(14.5,31.75) 14.5,31.6 15.03,31.07 R96.1@15.08,31.07 ; U18.13@16.73,34.02 U18.2@18.18,34.02 18.205,33.995 18.815,33.995 19.188,33.621 19.188,33.5 v1(19.319,33.5) ; D9.2@41.75,31.5 41.9,31.65 41.9,31.985 42.573,32.658 43.21,32.658 v1(44,33.448) ; C12.1@42.95,3.35 43,3.3 C12.1@43.1,3.2 43.3,3 R14.2@45.95,3 ; U16.2@49.741,14.5 U16.2@49.991,14.5 ; Q2.1@50.95,5.1 50.95,5.093 Q2.1@51.05,4.993 ; C16.1@51,2.825 C16.1@51.05,2.775 ; R18.2@52,2.775 R18.2@52.05,2.724 ; v1@53.875,3 v1(54,3) ; Q10.1@54.2,5.38 54.2,5.425 54.275,5.5 v1(55.25,5.5) ; U11.7@57.66,21.15 U11.7@57.705,21.195 ; v1@57.705,22.955 v1(57.75,23) ; v1@62.965,16.865 v1(63.1,16.865) ; R52.2@63.557,30.1 64.281,30.1 64.583,29.798 64.894,29.798 ; v1(65,29.25) 64.894,29.356 64.894,29.798 ; U7.2@65.607,30.275 65.607,30.2 65.204,29.798 64.894,29.798 ; C15.2@68.5,15.8 C15.2@68.6,15.8 ; C10.2@74.4,13.925 C10.2@74.4,14.025 ; 76.4,8.2 76.5,8.3
  Bottom Layer w0.25: v1(19,30) 19.016,29.984 19.016,29.066 R7.1@19.032,29.05 ; v1(30.5,22.188) 30.652,22.188 30.84,22 31.323,22 C25.1@32.25,22 ; C19.1@33.5,17.15 v1(33.5,16.5) 33.652,16.5 34.105,16.048 35.198,16.048 R43.2@35.7,16.55 ; C3.1@41,3.35 C12.1@42.95,3.35 ; C24.1@42,23.35 42,22.605 42.123,22.605 42.601,22.127 v1(42.75,22.127) ; C12.1@43,3.3 v1(43,4.5) ; C4.1@48.291,14.9 49.341,14.9 U16.2@49.741,14.5 ; U16.2@49.991,14.5 50.138,14.352 50.95,14.352 51.098,14.5 v1(51.25,14.5) 51.402,14.5 51.55,14.352 51.912,14.352 52.309,14.75 53.85,14.75 54,14.9 ; C16.1@51.05,2.775 R18.2@52,2.775 ; Q2.1@51.05,4.993 v1(52,4.993) ; R18.2@52.05,2.724 R17.2@53.1,2.724 53.6,2.724 v1@53.875,3 ; C13.1@54,14.15 54,14.9 ; U2.2@56.8,14.5 57.75,14.5 ; U11.7@57.705,21.195 v1@57.705,22.955 ; v1@62.965,16.865 C14.1@61.8,15.7 61.2,15.7 60,14.5 57.75,14.5 ; v1@63.1,17 65.25,17 66.045,16.205 66.045,15.3 ; U3.2@64.491,15.3 66.045,15.3 ; C15.2@68.5,15.8 68,15.3 66.045,15.3 ; 54,14.9 55.35,16.25 57.5,16.25 57.75,16 57.75,14.5
  Bottom Layer w0.254: v1(69.5,35.9) v1(70.9,35.9) 70.909,35.9 71.384,36.375 C1.2@72.5,36.375
  Bottom Layer w0.3: v1(10.25,4) D5.2@11.25,4 ; D4.2@17.5,4 17.525,4.025 18.725,4.025 R31.2@18.75,4.05 18.8,4.05 19.752,3.098 20.152,3.098 v1(20.25,3) ; v1@20.389,3 20.789,3.4 C35.1@23.01,3.4 ; v1(62,25) 62.05,25.05 63.06,25.05 C33.1@63.11,25.1 63.905,25.895 63.905,26.29 C34.1@64.015,26.4 64.04,26.375 65.192,26.375 R98.2@65.217,26.35 ; D3.1@65,5 65.05,5 65.15,5.1 65.15,5.15 67.779,7.779 J5.1@67.779,9.08 ; v1(70.5,21.9) U8.9@70.5,24.25 70.5,24.355 71.595,25.45 U8.5@72.5,25.45 73.443,25.45 73.611,25.619 v1(73.75,25.619) ; C1.2@72.5,36.375 72.655,36.375 73.72,37.44 74.5,37.44 C5.2@74.52,37.42 ; C10.2@74.4,13.925 75,13.325 v1(75,11.25) U1.2@75,10 75.15,9.85 75.15,9.35 75.525,8.975 75.525,8.2 ; C5.2@74.5,37.4 75.245,38.145 75.395,38.145 75.6,38.35 FB7.1@75.6,38.5 ; R49.2@74.65,8.2 75.525,8.2 ; 76.4,8.2 75.525,8.2 ; U9.5@80.9,26.405 81.781,26.405 81.936,26.25 v1(82.75,26.25) ; v1(99.25,10) 101,10 D6.2@101.85,9.15 ; D6.2@101.9,9.15 102,9.05 D6.2@102,9
  Bottom Layer w0.5: C11.2@4.08,26.42 R6.2@4.08,27.67 v1(4.08,29.252) 3.333,30 3.333,31.812 3.731,32.21 4.02,32.21 C7.1@4.03,32.22 4.51,32.7 D19.A@5.38,32.7 ; v1(9,33.25) 9.06,33.31 9.37,33.31 9.98,33.92 C8.1@10.08,33.92 11.255,33.92 11.58,34.245 C6.2@11.58,34.345
  Bottom Layer w0.8: v1(97.2,33.3) 98.1,34.2 98.34,34.2 98.645,34.505 98.655,34.505 FB20.1@98.7,34.55
  Bottom Layer w2: v1(10,43.5) v1(30,43.5) v1(40,43.5) v1(45,43.5) ; v1(54,43.5) v1(60,43.5) v1(70,43.5) v1(80,43.5) v1(85,43.5) ; v1(97,43.5) v1@103.4,43.5
  other v1: 10,1.5 20,1.5 30,1.5 40.75,1.5 50,1.5 60,1.5 70,1.5 80,1.5 85,1.5 97,1.5 103.5,1.5 67.8,5.4 1.5,10 103.5,15 1.5,20 95,20.5 19.75,22.25 98.75,22.25 98.75,23.25 89.25,24.5 103.5,25 98.55,28 94.993,28.257 1.5,30 85.5,30.5 95,32.5 1.5,35 85,35 103.5,35 10,40 20,40 45,40 54,40 19.988,43.513 103,43.5
HW_ID: R41.2 R43.1 U4.G5 | length 4.5
  Top Layer w0.152: v4(35.915,20.181) 35.917,20.178 35.917,19.803 U4.G5@35.92,19.8
  Bottom Layer w0.152: R41.2@34.8,16.55 34.85,16.55 35.551,17.251 35.551,17.301 35.7,17.45 R43.1@35.75,17.45 35.75,17.972 35.908,18.131 35.908,18.505 35.915,18.511 v4(35.915,20.181)
ID_BIAS: R41.1 U4.G4 | length 3.4
  Top Layer w0.152: U4.G4@35.52,19.8 35.524,19.804 35.524,20.177 v4(35.527,20.181)
  Bottom Layer w0.152: R41.1@34.8,17.45 34.85,17.45 34.999,17.599 34.999,17.95 35.527,18.479 v4(35.527,20.181)
L433_I2C3_SCL: R60.1 U4.H4 | length 16.3
  Top Layer w0.152: 27.65,11.75 27.674,11.726 ; v1@29.884,11.317 v1(30,11.317) ; v1(33.926,13.5) 34,13.574 34,14.5 34.752,15.252 34.752,16.514 34.879,16.641 34.879,17.721 v2(34.904,17.746)
  Top Layer w0.2: 25.7,11.75 27.65,11.75 29.451,11.75 v1@29.884,11.317
  Layer 2 w0.152: v2(34.904,17.746) 34.904,18.289 35.361,18.746 35.361,19.127 35.374,19.139 35.374,19.254 v3(35.383,19.263)
  Bottom Layer w0.152: v1@33.874,13.447 v1(33.926,13.5)
  Bottom Layer w0.25: v1(30,11.317) 30.096,11.222 32.472,11.222 33.874,12.624 v1@33.874,13.447
L433_I2C3_SDA: R73.1 U4.C6 | length 47
  Top Layer w0.152: R73.1@25.45,14 v1(26.5,14) ; v1(28.25,22.5) 28.124,22.626 27.274,22.626 26.748,22.1 23.4,22.1 22.327,23.173 22.327,24.245 22.699,24.617 25.278,24.617 25.309,24.586 30.086,24.586 31.25,25.75 31.25,26.235 30.248,27.237 30.248,27.763 32.865,30.38 33.47,30.38 33.59,30.5 34.48,30.5 v1(34.5,30.52) ; v4(35.889,20.994) 35.897,20.994 36.304,21.4 U4.C6@36.32,21.4
  Bottom Layer w0.152: v1(34.5,30.52) 35.135,29.885 35.135,28.964 35.06,28.889 35.06,25.348 35.889,24.519 v4(35.889,20.994)
  Bottom Layer w0.25: v1(26.5,14) 26.5,17.5 25.5,18.5 25.5,19.75 v1(28.25,22.5)
L476_I2C3_SCL: R97.1 U4.F9 | length 34.4
  Top Layer w0.152: 25.7,10.75 29.574,10.75 29.641,10.682 35.009,10.682 35.028,10.701 v1(40.701,10.701) ; U4.F9@37.52,20.2 38.009,20.2 38.498,19.711 40.039,19.711 40.86,18.89 45.326,18.89 v1(46.226,17.99)
  Bottom Layer w0.152: v1(40.701,10.701) v1@40.713,10.713
  Bottom Layer w0.2: v1@40.713,10.713 41.898,11.898 42.146,11.898 45.341,15.093 45.341,15.59 46.25,16.498 46.25,17.966 v1(46.226,17.99)
L476_I2C3_SDA: R51.1 U4.F8 | length 33.3
  Top Layer w0.152: R51.1@25.45,13 R51.1@25.65,13 ; U4.F8@37.12,20.2 v3(37.257,20.063) ; v2(39.019,19.33) 39.044,19.305 40.014,19.305 40.733,18.586 44.5,18.586 v1(45.043,18.043)
  Top Layer w0.2: R51.1@25.65,13 29.998,13 31.463,11.536 37.521,11.536 37.715,11.73 40.73,11.73 v1(41.25,12.25)
  Layer 2 w0.152: v3(37.257,20.063) 37.266,20.054 37.33,20.054 38.054,19.33 v2(39.019,19.33)
  Bottom Layer w0.2: v1(41.25,12.25) 42,12.25 44.989,15.239 44.989,16.472 45.043,16.526 v1(45.043,18.043)
LDO_EN: D8.3 R2.2 R49.1 R118.2 U1.3 | length 26.3
  Bottom Layer w0.2: R118.2@52.741,9.316 R2.2@53.841,9.316 53.841,9.266 54.607,8.5 56.5,8.5 58.7,10.7 70.3,10.7 71,10 U1.3@74.05,10 ; D8.3@73.75,6.741 D8.3@73.8,6.691 ; R49.1@73.75,8.2 R49.1@73.75,8.25
  Bottom Layer w0.3: D8.3@73.75,6.741 R49.1@73.75,8.2 ; R49.1@73.75,8.25 74.05,8.55 U1.3@74.05,10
